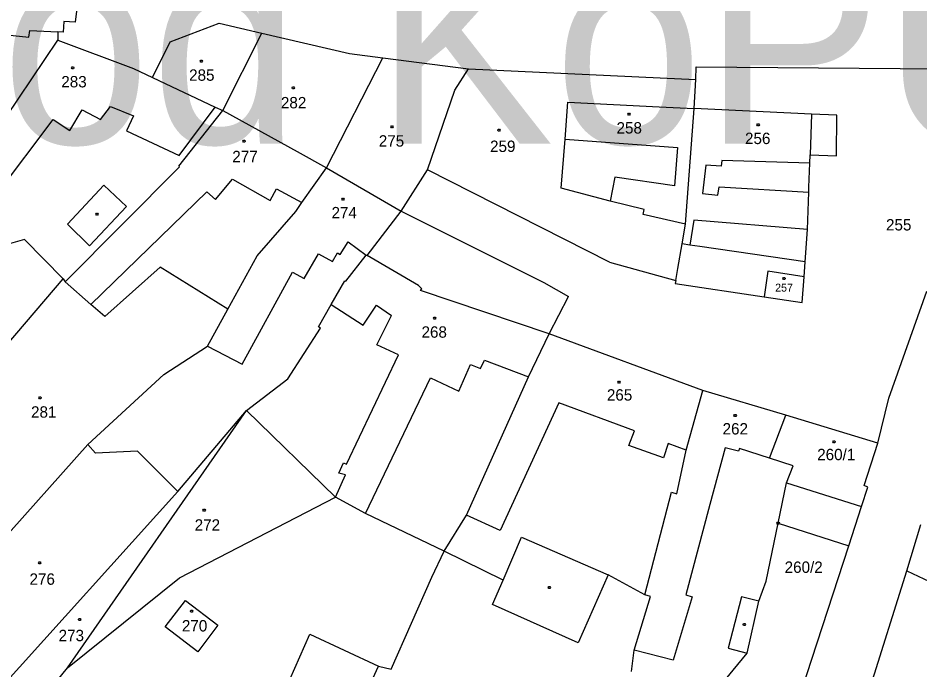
# Model space of a CAD drawing. Extents: x -634640 to -629202, y -1196156 to -1190068.
# Drawn here: x -631784.1 to -631649.3, y -1192720.1 to -1192622.8 of the extents above; entities that cross this region are included whole.
import ezdxf

# ---------------------------------------------------------------- set-up
doc = ezdxf.new("R2010")
doc.units = 0
for name, color, linetype in [('Obvod šetřený', 7, 'Continuous'), ('Vrstva 1', 7, 'Continuous'), ('Vrstva 2', 7, 'Continuous'), ('Vrstva 3', 7, 'Continuous'), ('Vrstva 4', 7, 'Continuous'), ('Vrstva 5', 7, 'Continuous'), ('Vrstva 8', 7, 'Continuous')]:
    doc.layers.add(name, color=color, linetype=linetype)

msp = doc.modelspace()

# ---------------------------------------------------------------- linework, layer by layer
at = {"layer": 'Vrstva 1'}
for p, q in [((-631774.77, -1192617.38), (-631775.53, -1192623.36)), ((-631777.22, -1192623.26), (-631777.31, -1192624.86)), ((-631775.53, -1192623.36), (-631777.22, -1192623.26)), ((-631761.34, -1192626.31), (-631754, -1192623.52)), ((-631754, -1192623.52), (-631747.62, -1192625.02)), ((-631778.11, -1192624.82), (-631778.13, -1192626.06)), ((-631777.31, -1192624.86), (-631778.11, -1192624.82)), ((-631753.49, -1192636.59), (-631747.62, -1192625.02)), ((-631747.62, -1192625.02), (-631734.54, -1192628.04)), ((-631785.88, -1192637.63), (-631778.13, -1192626.06)), ((-631778.13, -1192626.06), (-631766.82, -1192630.32)), ((-631763.96, -1192631.66), (-631761.34, -1192626.31)), ((-631734.54, -1192628.04), (-631729.58, -1192628.69)), ((-631737.97, -1192645.12), (-631729.58, -1192628.69)), ((-631729.58, -1192628.69), (-631716.79, -1192630.33)), ((-631766.82, -1192630.32), (-631763.96, -1192631.66)), ((-631718.82, -1192633.54), (-631716.79, -1192630.33)), ((-631716.79, -1192630.33), (-631688.13, -1192631.7)), ((-631682.81, -1192631.96), (-631682.78, -1192630.05)), ((-631682.78, -1192630.05), (-631639.53, -1192630.43)), ((-631763.96, -1192631.66), (-631754.62, -1192636.06)), ((-631688.13, -1192631.7), (-631682.81, -1192631.96)), ((-631683.07, -1192636.28), (-631682.81, -1192631.96)), ((-631722.88, -1192645.42), (-631718.82, -1192633.54)), ((-631702.34, -1192640.83), (-631701.95, -1192635.34)), ((-631701.95, -1192635.34), (-631688.28, -1192636.02)), ((-631760.06, -1192644.87), (-631753.49, -1192636.59)), ((-631754.62, -1192636.06), (-631753.49, -1192636.59)), ((-631753.49, -1192636.59), (-631742.36, -1192642.7)), ((-631688.28, -1192636.02), (-631683.07, -1192636.28)), ((-631684.35, -1192653.54), (-631683.07, -1192636.28)), ((-631665.52, -1192637.12), (-631683.07, -1192636.28)), ((-631661.76, -1192637.25), (-631665.52, -1192637.12)), ((-631661.83, -1192643.36), (-631661.76, -1192637.25)), ((-631702.93, -1192648.15), (-631702.34, -1192640.83)), ((-631742.36, -1192642.7), (-631737.97, -1192645.12)), ((-631665.79, -1192644.44), (-631665.74, -1192643.19)), ((-631665.74, -1192643.19), (-631661.83, -1192643.36)), ((-631665.92, -1192648.02), (-631665.79, -1192644.44)), ((-631777.02, -1192662.13), (-631759.93, -1192644.99)), ((-631759.93, -1192644.99), (-631760.06, -1192644.87)), ((-631741.66, -1192650.31), (-631737.97, -1192645.12)), ((-631737.97, -1192645.12), (-631726.81, -1192651.61)), ((-631726.81, -1192651.61), (-631722.88, -1192645.42)), ((-631695.73, -1192659.19), (-631722.88, -1192645.42)), ((-631695.59, -1192650.09), (-631702.93, -1192648.15)), ((-631666.15, -1192654.36), (-631665.95, -1192648.76)), ((-631665.95, -1192648.76), (-631665.92, -1192648.02)), ((-631690.55, -1192651.35), (-631695.59, -1192650.09)), ((-631742.58, -1192651.66), (-631741.66, -1192650.31)), ((-631690.71, -1192652.1), (-631690.55, -1192651.35)), ((-631748.32, -1192658.26), (-631742.58, -1192651.66)), ((-631731.92, -1192658.23), (-631726.81, -1192651.61)), ((-631726.81, -1192651.61), (-631705.53, -1192662.24)), ((-631684.35, -1192653.54), (-631690.71, -1192652.1)), ((-631684.86, -1192656.48), (-631684.35, -1192653.54)), ((-631666.49, -1192659.17), (-631666.15, -1192654.36)), ((-631783.11, -1192655.81), (-631785.16, -1192656.42)), ((-631777.31, -1192661.71), (-631783.11, -1192655.81)), ((-631685.51, -1192660.18), (-631684.86, -1192656.48)), ((-631683.72, -1192656.65), (-631684.86, -1192656.48)), ((-631682.23, -1192656.87), (-631683.72, -1192656.65)), ((-631666.49, -1192659.17), (-631682.23, -1192656.87)), ((-631735.1, -1192662.03), (-631732.05, -1192658.15)), ((-631732.05, -1192658.15), (-631731.92, -1192658.23)), ((-631752.73, -1192666.25), (-631748.32, -1192658.26)), ((-631695.73, -1192659.19), (-631685.82, -1192661.94)), ((-631666.65, -1192661.39), (-631666.49, -1192659.17)), ((-631762.83, -1192659.97), (-631771.1, -1192667.3)), ((-631752.73, -1192666.25), (-631762.83, -1192659.97)), ((-631685.82, -1192661.94), (-631685.51, -1192660.18)), ((-631792.92, -1192679.94), (-631777.31, -1192661.71)), ((-631777.31, -1192661.71), (-631777.02, -1192662.13)), ((-631773.17, -1192665.55), (-631777.02, -1192662.13)), ((-631737.28, -1192665.55), (-631735.24, -1192661.98)), ((-631735.24, -1192661.98), (-631735.1, -1192662.03)), ((-631705.53, -1192662.24), (-631701.84, -1192664.32)), ((-631685.82, -1192661.94), (-631685.9, -1192662.41)), ((-631666.93, -1192665.21), (-631666.65, -1192661.39)), ((-631685.9, -1192662.41), (-631672.62, -1192664.37)), ((-631653.99, -1192679.51), (-631648.32, -1192663.55)), ((-631704.73, -1192669.93), (-631701.84, -1192664.32)), ((-631672.62, -1192664.37), (-631666.93, -1192665.21)), ((-631771.1, -1192667.3), (-631773.17, -1192665.55)), ((-631755.75, -1192671.73), (-631752.73, -1192666.25)), ((-631739.19, -1192668.89), (-631737.28, -1192665.55)), ((-631738.9, -1192669.06), (-631739.19, -1192668.89)), ((-631743.77, -1192676.64), (-631738.9, -1192669.06)), ((-631707.82, -1192676.35), (-631704.73, -1192669.93)), ((-631681.77, -1192678.35), (-631704.73, -1192669.93)), ((-631762.26, -1192675.97), (-631755.75, -1192671.73)), ((-631773.62, -1192686.44), (-631762.26, -1192675.97)), ((-631749.92, -1192681.36), (-631743.77, -1192676.64)), ((-631717.09, -1192696.97), (-631707.82, -1192676.35)), ((-631684.25, -1192687.3), (-631681.77, -1192678.35)), ((-631669.37, -1192682.05), (-631681.77, -1192678.35)), ((-631655.63, -1192686.24), (-631653.99, -1192679.51)), ((-631776.66, -1192719.79), (-631749.92, -1192681.36)), ((-631760.2, -1192693.47), (-631749.92, -1192681.36)), ((-631736.64, -1192694.32), (-631749.92, -1192681.36)), ((-631671.82, -1192688.48), (-631669.37, -1192682.05)), ((-631655.63, -1192686.24), (-631669.37, -1192682.05)), ((-631792.06, -1192707.08), (-631773.62, -1192686.44)), ((-631772.47, -1192687.74), (-631773.62, -1192686.44)), ((-631657.69, -1192692.56), (-631655.63, -1192686.24)), ((-631766.21, -1192687.42), (-631772.47, -1192687.74)), ((-631760.2, -1192693.47), (-631766.21, -1192687.42)), ((-631685.64, -1192693.78), (-631684.25, -1192687.3)), ((-631668.28, -1192689.62), (-631671.82, -1192688.48)), ((-631669.26, -1192692.14), (-631668.28, -1192689.62)), ((-631670.52, -1192698.19), (-631669.26, -1192692.14)), ((-631658.09, -1192695.69), (-631657.14, -1192692.81)), ((-631657.14, -1192692.81), (-631657.69, -1192692.56)), ((-631787.93, -1192724.11), (-631760.2, -1192693.47)), ((-631759.93, -1192706.33), (-631736.64, -1192694.32)), ((-631732.18, -1192696.72), (-631736.64, -1192694.32)), ((-631690.45, -1192708.86), (-631686.47, -1192693.55)), ((-631686.47, -1192693.55), (-631685.64, -1192693.78)), ((-631659.98, -1192701.55), (-631658.09, -1192695.69)), ((-631720.39, -1192702.36), (-631732.18, -1192696.72)), ((-631720.39, -1192702.36), (-631717.09, -1192696.97)), ((-631672.32, -1192706.83), (-631670.52, -1192698.19)), ((-631670.52, -1192698.19), (-631659.98, -1192701.55)), ((-631651.28, -1192705.28), (-631649.2, -1192698.38)), ((-631722.26, -1192706.23), (-631720.39, -1192702.36)), ((-631711.62, -1192706.67), (-631720.39, -1192702.36)), ((-631668.3, -1192727.1), (-631659.98, -1192701.55)), ((-631666.42, -1192753.44), (-631651.28, -1192705.28)), ((-631651.28, -1192705.28), (-631646.21, -1192707.68)), ((-631776.66, -1192719.79), (-631759.93, -1192706.33)), ((-631728.31, -1192719.98), (-631722.26, -1192706.23)), ((-631713.19, -1192710.33), (-631711.62, -1192706.67)), ((-631695.9, -1192705.88), (-631700.41, -1192716.05)), ((-631690.45, -1192708.86), (-631695.9, -1192705.88)), ((-631673.4, -1192709.81), (-631672.32, -1192706.83)), ((-631692.04, -1192717.12), (-631689.57, -1192709.13)), ((-631689.57, -1192709.13), (-631690.45, -1192708.86)), ((-631762.08, -1192713.66), (-631759.04, -1192709.72)), ((-631759.04, -1192709.72), (-631754.2, -1192713.41)), ((-631700.41, -1192716.05), (-631713.19, -1192710.33)), ((-631675.17, -1192717.6), (-631673.4, -1192709.81)), ((-631754.2, -1192713.41), (-631757.22, -1192717.37)), ((-631757.22, -1192717.37), (-631762.08, -1192713.66)), ((-631751.5, -1192739.61), (-631740.47, -1192714.76)), ((-631740.47, -1192714.76), (-631730.23, -1192719.55)), ((-631692.44, -1192720.33), (-631692.04, -1192717.12)), ((-631680.25, -1192723.75), (-631675.17, -1192717.6)), ((-631783.13, -1192727.65), (-631776.66, -1192719.79)), ((-631738.56, -1192737.86), (-631730.23, -1192719.55)), ((-631730.23, -1192719.55), (-631728.31, -1192719.98))]:
    msp.add_line(p, q, dxfattribs=at)
at = {"layer": 'Vrstva 3'}
for points in [[(-631756.58, -1192629.06), (-631756.49, -1192629.21), (-631756.58, -1192629.36), (-631756.76, -1192629.36), (-631756.85, -1192629.21), (-631756.76, -1192629.06), (-631756.58, -1192629.06)], [(-631742.86, -1192633.04), (-631742.77, -1192633.19), (-631742.86, -1192633.34), (-631743.04, -1192633.34), (-631743.13, -1192633.19), (-631743.04, -1192633.04), (-631742.86, -1192633.04)], [(-631728.11, -1192638.84), (-631728.02, -1192638.99), (-631728.11, -1192639.14), (-631728.29, -1192639.14), (-631728.38, -1192638.99), (-631728.29, -1192638.84), (-631728.11, -1192638.84)], [(-631712.14, -1192639.36), (-631712.05, -1192639.51), (-631712.14, -1192639.66), (-631712.32, -1192639.66), (-631712.41, -1192639.51), (-631712.32, -1192639.36), (-631712.14, -1192639.36)], [(-631780.67, -1192679.34), (-631780.58, -1192679.49), (-631780.67, -1192679.64), (-631780.85, -1192679.64), (-631780.94, -1192679.49), (-631780.85, -1192679.34), (-631780.67, -1192679.34)], [(-631756.16, -1192696.07), (-631756.07, -1192696.22), (-631756.16, -1192696.37), (-631756.34, -1192696.37), (-631756.43, -1192696.22), (-631756.34, -1192696.07), (-631756.16, -1192696.07)], [(-631780.74, -1192703.97), (-631780.65, -1192704.12), (-631780.74, -1192704.27), (-631780.92, -1192704.27), (-631781.01, -1192704.12), (-631780.92, -1192703.97), (-631780.74, -1192703.97)], [(-631774.77, -1192712.4), (-631774.68, -1192712.55), (-631774.77, -1192712.7), (-631774.95, -1192712.7), (-631775.04, -1192712.55), (-631774.95, -1192712.4), (-631774.77, -1192712.4)]]:
    msp.add_lwpolyline(points, dxfattribs=at)
at = {"layer": 'Vrstva 4'}
for p, q in [((-631787.42, -1192625.1), (-631782.46, -1192625.6)), ((-631782.46, -1192625.6), (-631782.31, -1192624.63)), ((-631782.31, -1192624.63), (-631778.11, -1192624.82)), ((-631776.34, -1192639.57), (-631774.5, -1192636.49)), ((-631774.5, -1192636.49), (-631771.75, -1192637.92)), ((-631771.75, -1192637.92), (-631770.23, -1192635.98)), ((-631770.23, -1192635.98), (-631766.8, -1192637.37)), ((-631759.98, -1192643.28), (-631754.62, -1192636.06)), ((-631789.83, -1192652.53), (-631778.83, -1192637.89)), ((-631778.83, -1192637.89), (-631776.34, -1192639.57)), ((-631766.8, -1192637.37), (-631767.84, -1192639.61)), ((-631665.52, -1192637.12), (-631665.74, -1192643.19)), ((-631767.84, -1192639.61), (-631759.98, -1192643.28)), ((-631702.34, -1192640.83), (-631685.56, -1192642.11)), ((-631685.56, -1192642.11), (-631685.99, -1192647.81)), ((-631681.35, -1192644.73), (-631681.84, -1192648.94)), ((-631679.06, -1192644.9), (-631681.35, -1192644.73)), ((-631678.93, -1192644.04), (-631679.06, -1192644.9)), ((-631665.79, -1192644.44), (-631678.93, -1192644.04)), ((-631754.58, -1192649.85), (-631752.04, -1192646.82)), ((-631752.04, -1192646.82), (-631746.41, -1192649.99)), ((-631694.94, -1192646.52), (-631695.59, -1192650.09)), ((-631685.99, -1192647.81), (-631694.94, -1192646.52)), ((-631776.69, -1192653.54), (-631771.22, -1192647.74)), ((-631773.17, -1192665.55), (-631755.88, -1192648.69)), ((-631771.22, -1192647.74), (-631767.85, -1192650.92)), ((-631755.88, -1192648.69), (-631754.58, -1192649.85)), ((-631746.41, -1192649.99), (-631745.46, -1192648.24)), ((-631745.46, -1192648.24), (-631741.66, -1192650.31)), ((-631679.52, -1192649.21), (-631679.35, -1192647.98)), ((-631679.35, -1192647.98), (-631665.95, -1192648.76)), ((-631681.84, -1192648.94), (-631679.52, -1192649.21)), ((-631767.85, -1192650.92), (-631773.4, -1192656.77)), ((-631773.4, -1192656.77), (-631776.69, -1192653.54)), ((-631683.12, -1192652.93), (-631683.72, -1192656.65)), ((-631666.15, -1192654.36), (-631683.12, -1192652.93)), ((-631735.95, -1192658.07), (-631734.76, -1192656.18)), ((-631734.76, -1192656.18), (-631732.05, -1192658.15)), ((-631741.31, -1192661.67), (-631739.2, -1192657.95)), ((-631739.2, -1192657.95), (-631737.1, -1192659.11)), ((-631737.1, -1192659.11), (-631736.36, -1192657.8)), ((-631736.36, -1192657.8), (-631735.95, -1192658.07)), ((-631724.22, -1192662.72), (-631731.92, -1192658.23)), ((-631750.6, -1192674.45), (-631743.07, -1192660.71)), ((-631743.07, -1192660.71), (-631741.31, -1192661.67)), ((-631672.09, -1192660.58), (-631672.62, -1192664.37)), ((-631666.65, -1192661.39), (-631672.09, -1192660.58)), ((-631723.73, -1192663.17), (-631724.22, -1192662.72)), ((-631723.95, -1192663.42), (-631723.73, -1192663.17)), ((-631704.73, -1192669.93), (-631723.95, -1192663.42)), ((-631737.28, -1192665.55), (-631732.5, -1192668.6)), ((-631732.5, -1192668.6), (-631730.51, -1192665.61)), ((-631730.51, -1192665.61), (-631728.29, -1192667.16)), ((-631730.46, -1192671.56), (-631728.29, -1192667.16)), ((-631727.24, -1192673.06), (-631730.46, -1192671.56)), ((-631755.75, -1192671.73), (-631750.6, -1192674.45)), ((-631734.98, -1192689.36), (-631727.24, -1192673.06)), ((-631714.98, -1192675.08), (-631714.4, -1192673.86)), ((-631714.4, -1192673.86), (-631707.82, -1192676.35)), ((-631718.22, -1192678.47), (-631716.47, -1192674.51)), ((-631716.47, -1192674.51), (-631714.98, -1192675.08)), ((-631732.18, -1192696.72), (-631722.44, -1192676.5)), ((-631722.44, -1192676.5), (-631718.22, -1192678.47)), ((-631703.3, -1192680.23), (-631712.03, -1192699.29)), ((-631692, -1192684.4), (-631703.3, -1192680.23)), ((-631692.84, -1192686.56), (-631692, -1192684.4)), ((-631686.95, -1192686.29), (-631687.64, -1192688.45)), ((-631684.25, -1192687.3), (-631686.95, -1192686.29)), ((-631687.64, -1192688.45), (-631692.84, -1192686.56)), ((-631678.46, -1192686.94), (-631680.72, -1192695.39)), ((-631677.03, -1192687.29), (-631678.46, -1192686.94)), ((-631676.46, -1192687.42), (-631677.03, -1192687.29)), ((-631676.32, -1192687.05), (-631676.46, -1192687.42)), ((-631671.82, -1192688.48), (-631676.32, -1192687.05)), ((-631736.15, -1192690.72), (-631735.46, -1192689.19)), ((-631735.46, -1192689.19), (-631734.98, -1192689.36)), ((-631736.64, -1192694.32), (-631735.16, -1192690.97)), ((-631735.16, -1192690.97), (-631736.15, -1192690.72)), ((-631669.26, -1192692.14), (-631658.09, -1192695.69)), ((-631680.72, -1192695.39), (-631684.33, -1192708.9)), ((-631712.03, -1192699.29), (-631717.09, -1192696.97)), ((-631711.62, -1192706.67), (-631708.87, -1192700.27)), ((-631708.87, -1192700.27), (-631695.9, -1192705.88)), ((-631683.38, -1192709.19), (-631686.18, -1192718.63)), ((-631684.33, -1192708.9), (-631683.38, -1192709.19)), ((-631676.01, -1192709.2), (-631677.98, -1192716.82)), ((-631673.4, -1192709.81), (-631676.01, -1192709.2)), ((-631686.18, -1192718.63), (-631692.04, -1192717.12)), ((-631677.98, -1192716.82), (-631675.17, -1192717.6))]:
    msp.add_line(p, q, dxfattribs=at)
at = {"layer": 'Vrstva 5'}
for points in [[(-631775.79, -1192630.06), (-631775.7, -1192630.21), (-631775.79, -1192630.36), (-631775.97, -1192630.36), (-631776.06, -1192630.21), (-631775.97, -1192630.06), (-631775.79, -1192630.06)], [(-631692.71, -1192636.96), (-631692.62, -1192637.11), (-631692.71, -1192637.26), (-631692.89, -1192637.26), (-631692.98, -1192637.11), (-631692.89, -1192636.96), (-631692.71, -1192636.96)], [(-631673.42, -1192638.58), (-631673.33, -1192638.73), (-631673.42, -1192638.88), (-631673.6, -1192638.88), (-631673.69, -1192638.73), (-631673.6, -1192638.58), (-631673.42, -1192638.58)], [(-631750.2, -1192641.02), (-631750.11, -1192641.17), (-631750.2, -1192641.32), (-631750.38, -1192641.32), (-631750.47, -1192641.17), (-631750.38, -1192641.02), (-631750.2, -1192641.02)], [(-631735.43, -1192649.68), (-631735.34, -1192649.83), (-631735.43, -1192649.98), (-631735.61, -1192649.98), (-631735.7, -1192649.83), (-631735.61, -1192649.68), (-631735.43, -1192649.68)], [(-631772.17, -1192651.89), (-631772.08, -1192652.04), (-631772.17, -1192652.19), (-631772.35, -1192652.19), (-631772.44, -1192652.04), (-631772.35, -1192651.89), (-631772.17, -1192651.89)], [(-631669.55, -1192661.48), (-631669.46, -1192661.63), (-631669.55, -1192661.78), (-631669.73, -1192661.78), (-631669.82, -1192661.63), (-631669.73, -1192661.48), (-631669.55, -1192661.48)], [(-631721.74, -1192667.4), (-631721.65, -1192667.55), (-631721.74, -1192667.7), (-631721.92, -1192667.7), (-631722.01, -1192667.55), (-631721.92, -1192667.4), (-631721.74, -1192667.4)], [(-631694.21, -1192677), (-631694.12, -1192677.15), (-631694.21, -1192677.3), (-631694.39, -1192677.3), (-631694.48, -1192677.15), (-631694.39, -1192677), (-631694.21, -1192677)], [(-631676.85, -1192681.94), (-631676.76, -1192682.09), (-631676.85, -1192682.24), (-631677.03, -1192682.24), (-631677.12, -1192682.09), (-631677.03, -1192681.94), (-631676.85, -1192681.94)], [(-631662.08, -1192685.9), (-631661.99, -1192686.05), (-631662.08, -1192686.2), (-631662.26, -1192686.2), (-631662.35, -1192686.05), (-631662.26, -1192685.9), (-631662.08, -1192685.9)], [(-631704.62, -1192707.65), (-631704.53, -1192707.8), (-631704.62, -1192707.95), (-631704.8, -1192707.95), (-631704.89, -1192707.8), (-631704.8, -1192707.65), (-631704.62, -1192707.65)], [(-631758.05, -1192711.18), (-631757.96, -1192711.33), (-631758.05, -1192711.48), (-631758.23, -1192711.48), (-631758.32, -1192711.33), (-631758.23, -1192711.18), (-631758.05, -1192711.18)], [(-631675.5, -1192713.14), (-631675.41, -1192713.29), (-631675.5, -1192713.44), (-631675.68, -1192713.44), (-631675.77, -1192713.29), (-631675.68, -1192713.14), (-631675.5, -1192713.14)]]:
    msp.add_lwpolyline(points, dxfattribs=at)
at = {"layer": 'Vrstva 8'}
msp.add_lwpolyline([(-631670.43, -1192698.04), (-631670.34, -1192698.19), (-631670.43, -1192698.34), (-631670.61, -1192698.34), (-631670.7, -1192698.19), (-631670.61, -1192698.04), (-631670.43, -1192698.04)], dxfattribs=at)

# ---------------------------------------------------------------- texts
at = {"layer": 'Obvod šetřený'}
msp.add_text('mimo obvod KoPÚ', height=30, dxfattribs=at).set_placement((-631960.455, -1192641.53))
at = {"layer": 'Vrstva 2'}
for s, height, p in [('285', 1.7, (-631758.503, -1192632.13)), ('283', 1.7, (-631777.593, -1192633.12)), ('282', 1.7, (-631744.793, -1192636.25)), ('258', 1.7, (-631694.663, -1192640.01)), ('275', 1.7, (-631730.173, -1192641.96)), ('256', 1.7, (-631675.473, -1192641.58)), ('259', 1.7, (-631713.553, -1192642.76)), ('277', 1.7, (-631752.053, -1192644.29)), ('274', 1.7, (-631737.233, -1192652.67)), ('255', 1.7, (-631654.413, -1192654.48)), ('257', 1.19, (-631670.974, -1192663.61)), ('268', 1.7, (-631723.793, -1192670.49)), ('265', 1.7, (-631696.103, -1192679.88)), ('281', 1.7, (-631782.113, -1192682.43)), ('262', 1.7, (-631678.823, -1192684.94)), ('260/1', 1.7, (-631664.693, -1192688.78)), ('272', 1.7, (-631757.673, -1192699.3)), ('260/2', 1.7, (-631669.553, -1192705.6)), ('276', 1.7, (-631782.343, -1192707.38)), ('270', 1.7, (-631759.583, -1192714.35)), ('273', 1.7, (-631777.993, -1192715.8))]:
    msp.add_text(s, height=height, dxfattribs=at).set_placement(p)

doc.saveas('drawing.dxf')
